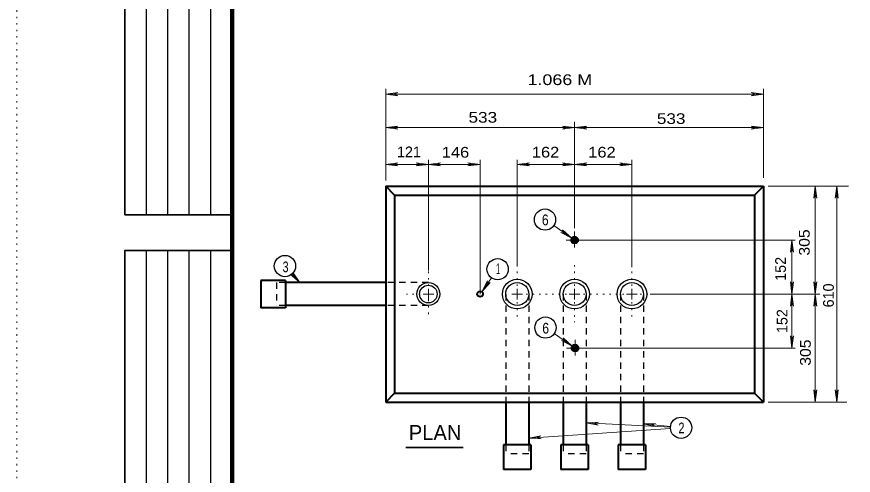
# Model space of a CAD drawing. Extents: x 312583 to 312854, y 144419 to 144597.
# Drawn here: x 312601.2 to 312660.6, y 144472.2 to 144504.7 of the extents above; entities that cross this region are included whole.
import ezdxf
from ezdxf.enums import TextEntityAlignment as Align

# ---------------------------------------------------------------- set-up
doc = ezdxf.new("R2010")
doc.units = 0
doc.header["$LTSCALE"] = 0.3
doc.linetypes.add('DOTTED', pattern=[1.5, 0.3, -1.2])
doc.linetypes.add('SHORT_DASHED', pattern=[2.7, 1.5, -1.2])
for name, color, linetype, lineweight in [('1', 7, 'Continuous', 25), ('2', 7, 'Continuous', 13), ('63', 7, 'DOTTED', 13)]:
    doc.layers.add(name, color=color, linetype=linetype, lineweight=lineweight)

msp = doc.modelspace()

# ---------------------------------------------------------------- linework, layer by layer
at = {"layer": '1'}
for p, q in [((312610.4087, 144490.6573), (312610.4087, 144521.8756)), ((312611.9315, 144490.6573), (312611.9315, 144521.8756)), ((312613.4543, 144490.6573), (312613.4543, 144521.8756)), ((312614.9772, 144490.6573), (312614.9772, 144521.8756)), ((312610.4087, 144456.901), (312610.4087, 144488.1192)), ((312611.9315, 144456.901), (312611.9315, 144488.1192)), ((312613.4543, 144456.901), (312613.4543, 144488.1192)), ((312614.9772, 144456.901), (312614.9772, 144488.1192))]:
    msp.add_line(p, q, dxfattribs=at)
at = {"layer": '1', "lineweight": 40}
for p, q in [((312627.4036, 144492.6869), (312654.237, 144492.6869)), ((312627.4036, 144492.6869), (312627.4036, 144477.3535)), ((312628.04, 144492.0505), (312627.4036, 144492.6869)), ((312653.6006, 144492.0505), (312654.237, 144492.6869)), ((312654.237, 144492.6869), (312654.237, 144477.3535)), ((312628.04, 144492.0505), (312653.6006, 144492.0505)), ((312628.04, 144492.0505), (312628.04, 144477.9975)), ((312653.6006, 144492.0505), (312653.6006, 144477.9975)), ((312620.2813, 144485.9939), (312618.5256, 144485.9939)), ((312618.5256, 144485.9939), (312618.5256, 144484.0465)), ((312620.2813, 144485.9939), (312620.2813, 144484.0465)), ((312627.4036, 144485.8329), (312620.2813, 144485.8329)), ((312620.2813, 144484.0465), (312618.5256, 144484.0465)), ((312627.4036, 144484.2075), (312620.2813, 144484.2075)), ((312627.4036, 144477.3535), (312628.04, 144477.9975)), ((312628.04, 144477.9975), (312653.6006, 144477.9975)), ((312653.6006, 144477.9975), (312654.237, 144477.3535)), ((312627.4036, 144477.3535), (312654.237, 144477.3535)), ((312635.929, 144477.3535), (312635.929, 144474.3175)), ((312637.562, 144477.3535), (312637.562, 144474.3175)), ((312640.0076, 144477.3535), (312640.0076, 144474.3175)), ((312641.633, 144477.3535), (312641.633, 144474.3175)), ((312644.0786, 144477.3535), (312644.0786, 144474.3175)), ((312645.704, 144477.3535), (312645.704, 144474.3175)), ((312635.7756, 144474.3175), (312635.7756, 144472.5619)), ((312637.723, 144474.3175), (312635.7756, 144474.3175)), ((312637.723, 144474.3175), (312637.723, 144472.5619)), ((312639.8466, 144474.3175), (312639.8466, 144472.5619)), ((312641.794, 144474.3175), (312639.8466, 144474.3175)), ((312641.794, 144474.3175), (312641.794, 144472.5619)), ((312643.9176, 144474.3175), (312643.9176, 144472.5619)), ((312645.865, 144474.3175), (312643.9176, 144474.3175)), ((312645.865, 144474.3175), (312645.865, 144472.5619)), ((312637.723, 144472.5619), (312635.7756, 144472.5619)), ((312641.794, 144472.5619), (312639.8466, 144472.5619)), ((312645.865, 144472.5619), (312643.9176, 144472.5619))]:
    msp.add_line(p, q, dxfattribs=at)
at = {"layer": '1', "linetype": 'SHORT_DASHED'}
for p, q in [((312619.645, 144485.8329), (312619.645, 144484.2075)), ((312620.2813, 144485.8329), (312619.645, 144485.8329)), ((312630.4396, 144485.8329), (312627.4036, 144485.8329)), ((312635.929, 144485.0202), (312635.929, 144477.3535)), ((312637.562, 144485.0202), (312637.562, 144477.3535)), ((312640.0076, 144485.0202), (312640.0076, 144477.3535)), ((312641.633, 144485.0202), (312641.633, 144477.3535)), ((312644.0786, 144485.0202), (312644.0786, 144477.3535)), ((312645.704, 144485.0202), (312645.704, 144477.3535)), ((312620.2813, 144484.2075), (312619.645, 144484.2075)), ((312630.4396, 144484.2075), (312627.4036, 144484.2075)), ((312635.929, 144474.3175), (312635.929, 144473.6812)), ((312637.562, 144474.3175), (312637.562, 144473.6812)), ((312640.0076, 144474.3175), (312640.0076, 144473.6812)), ((312641.633, 144474.3175), (312641.633, 144473.6812)), ((312644.0786, 144474.3175), (312644.0786, 144473.6812)), ((312645.704, 144474.3175), (312645.704, 144473.6812)), ((312637.562, 144473.6812), (312635.929, 144473.6812)), ((312641.633, 144473.6812), (312640.0076, 144473.6812)), ((312645.704, 144473.6812), (312644.0786, 144473.6812))]:
    msp.add_line(p, q, dxfattribs=at)
at = {"layer": '1', "lineweight": 158}
msp.add_lwpolyline([(312616.5, 144423.1446), (312616.5, 144585.0846), (312849, 144585.0846)], dxfattribs=at)
at = {"layer": '1', "lineweight": 35}
for points in [[(312616.5, 144490.6573), (312608.8858, 144490.6573), (312608.8858, 144521.8756), (312616.5, 144521.8756)], [(312616.5, 144456.901), (312608.8858, 144456.901), (312608.8858, 144488.1192), (312616.5, 144488.1192)]]:
    msp.add_lwpolyline(points, dxfattribs=at)
at = {"layer": '1', "lineweight": 40}
for centre, radius in [((312640.8197, 144488.8548), 0.2396), ((312640.8197, 144488.8548), 0.2156), ((312640.8197, 144488.8548), 0.1941), ((312640.8197, 144488.8548), 0.1747), ((312640.8197, 144488.8548), 0.1572), ((312640.8197, 144488.8548), 0.1415), ((312640.8197, 144488.8548), 0.1273), ((312640.8197, 144488.8548), 0.1146), ((312640.8197, 144488.8548), 0.1031), ((312640.8197, 144488.8548), 0.0928), ((312640.8197, 144488.8548), 0.0835), ((312640.8197, 144488.8548), 0.0752), ((312640.8197, 144488.8548), 0.0677), ((312640.8197, 144488.8548), 0.0609), ((312640.8197, 144488.8548), 0.0548), ((312634.1113, 144485.0215), 0.1996), ((312640.8516, 144481.1881), 0.2396), ((312640.8516, 144481.1881), 0.2156), ((312640.8516, 144481.1881), 0.1941), ((312640.8516, 144481.1881), 0.1747), ((312640.8516, 144481.1881), 0.1572), ((312640.8516, 144481.1881), 0.1415), ((312640.8516, 144481.1881), 0.1273), ((312640.8516, 144481.1881), 0.1146), ((312640.8516, 144481.1881), 0.1031), ((312640.8516, 144481.1881), 0.0928), ((312640.8516, 144481.1881), 0.0835), ((312640.8516, 144481.1881), 0.0752), ((312640.8516, 144481.1881), 0.0677), ((312640.8516, 144481.1881), 0.0609), ((312640.8516, 144481.1881), 0.0548)]:
    msp.add_circle(centre, radius, dxfattribs=at)
at = {"layer": '1'}
for centre, radius in [((312630.4377, 144485.0215), 0.8146), ((312636.7467, 144485.0215), 1.0542), ((312636.7467, 144485.0215), 0.8146), ((312640.8197, 144485.0215), 1.0542), ((312640.8197, 144485.0215), 0.8146), ((312644.8926, 144485.0215), 1.0542), ((312644.8926, 144485.0215), 0.8146), ((312630.4377, 144485.0215), 0.6232)]:
    msp.add_circle(centre, radius, dxfattribs=at)
at = {"layer": '2'}
for p, q in [((312627.4036, 144493.0855), (312627.4036, 144499.5792)), ((312627.4036, 144499.2112), (312628.27, 144499.3185)), ((312628.27, 144499.3185), (312627.994, 144499.2112)), ((312653.3706, 144499.3185), (312653.6466, 144499.2112)), ((312654.237, 144499.2112), (312653.3706, 144499.3185)), ((312654.237, 144493.2772), (312654.237, 144499.5792)), ((312627.4036, 144499.2112), (312654.237, 144499.2112)), ((312627.4036, 144499.2112), (312628.27, 144499.1039)), ((312628.27, 144499.1039), (312627.994, 144499.2112)), ((312653.3706, 144499.1039), (312653.6466, 144499.2112)), ((312654.237, 144499.2112), (312653.3706, 144499.1039)), ((312627.4036, 144496.8422), (312628.27, 144496.9495)), ((312628.27, 144496.9495), (312627.994, 144496.8422)), ((312639.954, 144496.9495), (312640.23, 144496.8422)), ((312640.8203, 144496.8422), (312639.954, 144496.9495)), ((312640.8203, 144489.6892), (312640.8203, 144497.2562)), ((312640.8203, 144496.8422), (312641.6866, 144496.9495)), ((312641.6866, 144496.9495), (312641.4106, 144496.8422)), ((312653.3706, 144496.9495), (312653.6466, 144496.8422)), ((312654.237, 144496.8422), (312653.3706, 144496.9495)), ((312627.4036, 144496.8422), (312628.27, 144496.7349)), ((312627.4036, 144496.8422), (312642.1006, 144496.8422)), ((312628.27, 144496.7349), (312627.994, 144496.8422)), ((312628.04, 144496.8422), (312640.8203, 144496.8422)), ((312639.954, 144496.7349), (312640.23, 144496.8422)), ((312640.8203, 144496.8422), (312639.954, 144496.7349)), ((312640.8203, 144496.8422), (312654.237, 144496.8422)), ((312640.8203, 144496.8422), (312641.6866, 144496.7349)), ((312641.6866, 144496.7349), (312641.4106, 144496.8422)), ((312653.3706, 144496.7349), (312653.6466, 144496.8422)), ((312654.237, 144496.8422), (312653.3706, 144496.7349)), ((312627.4036, 144494.2279), (312628.27, 144494.3352)), ((312627.4036, 144494.2279), (312630.4396, 144494.2279)), ((312627.4036, 144494.2279), (312628.27, 144494.1205)), ((312628.27, 144494.3352), (312627.994, 144494.2279)), ((312628.27, 144494.1205), (312627.994, 144494.2279)), ((312629.5733, 144494.3352), (312629.8493, 144494.2279)), ((312630.4396, 144494.2279), (312629.5733, 144494.3352)), ((312629.5733, 144494.1205), (312629.8493, 144494.2279)), ((312630.4396, 144494.2279), (312629.5733, 144494.1205)), ((312630.4396, 144486.6839), (312630.4396, 144494.5422)), ((312630.4396, 144494.2279), (312631.306, 144494.3352)), ((312630.4396, 144494.2279), (312634.112, 144494.2279)), ((312630.4396, 144494.2279), (312631.306, 144494.1205)), ((312631.306, 144494.3352), (312631.03, 144494.2279)), ((312631.306, 144494.1205), (312631.03, 144494.2279)), ((312633.2456, 144494.3352), (312633.5216, 144494.2279)), ((312634.112, 144494.2279), (312633.2456, 144494.3352)), ((312633.2456, 144494.1205), (312633.5216, 144494.2279)), ((312634.112, 144494.2279), (312633.2456, 144494.1205)), ((312634.112, 144485.0202), (312634.112, 144494.5422)), ((312636.7493, 144487.0059), (312636.7493, 144494.5422)), ((312636.7493, 144494.2279), (312637.6156, 144494.3352)), ((312636.7493, 144494.2279), (312637.6156, 144494.1205)), ((312636.7493, 144494.2279), (312640.8203, 144494.2279)), ((312637.6156, 144494.3352), (312637.3396, 144494.2279)), ((312637.6156, 144494.1205), (312637.3396, 144494.2279)), ((312639.954, 144494.3352), (312640.23, 144494.2279)), ((312640.8203, 144494.2279), (312639.954, 144494.3352)), ((312639.954, 144494.1205), (312640.23, 144494.2279)), ((312640.8203, 144494.2279), (312639.954, 144494.1205)), ((312640.8203, 144494.2279), (312641.6866, 144494.3352)), ((312640.8203, 144494.2279), (312644.8913, 144494.2279)), ((312640.8203, 144494.2279), (312641.6866, 144494.1205)), ((312641.6866, 144494.3352), (312641.4106, 144494.2279)), ((312641.6866, 144494.1205), (312641.4106, 144494.2279)), ((312644.025, 144494.3352), (312644.301, 144494.2279)), ((312644.8913, 144494.2279), (312644.025, 144494.3352)), ((312644.025, 144494.1205), (312644.301, 144494.2279)), ((312644.8913, 144494.2279), (312644.025, 144494.1205)), ((312644.8913, 144486.9215), (312644.8913, 144494.5422)), ((312654.5666, 144492.6869), (312660.2632, 144492.6869)), ((312657.9134, 144492.6869), (312657.8061, 144491.8205)), ((312657.9134, 144492.6869), (312658.0208, 144491.8205)), ((312659.4375, 144492.6869), (312659.3302, 144491.8205)), ((312659.4375, 144477.3535), (312659.4375, 144492.6869)), ((312659.4375, 144492.6869), (312659.5449, 144491.8205)), ((312657.8061, 144491.8205), (312657.9134, 144492.0965)), ((312658.0208, 144491.8205), (312657.9134, 144492.0965)), ((312659.3302, 144491.8205), (312659.4375, 144492.0965)), ((312659.5449, 144491.8205), (312659.4375, 144492.0965)), ((312639.3406, 144489.8809), (312640.621, 144488.9915)), ((312639.8466, 144489.3979), (312640.138, 144489.3289)), ((312640.621, 144488.9915), (312639.8466, 144489.3979)), ((312639.9693, 144489.5742), (312640.138, 144489.3289)), ((312640.621, 144488.9915), (312639.9693, 144489.5742)), ((312640.8203, 144488.3245), (312640.8203, 144489.4515)), ((312641.3493, 144488.8535), (312640.2223, 144488.8535)), ((312640.943, 144488.8535), (312656.491, 144488.8535)), ((312656.261, 144488.8535), (312656.1536, 144487.9872)), ((312656.261, 144488.8535), (312656.3683, 144487.9872)), ((312656.1536, 144487.9872), (312656.261, 144488.2632)), ((312656.3683, 144487.9872), (312656.261, 144488.2632)), ((312620.6493, 144486.4079), (312620.9176, 144486.2775)), ((312621.3163, 144485.8329), (312620.6493, 144486.4079)), ((312620.7566, 144486.4539), (312621.3163, 144485.8329)), ((312620.8103, 144486.5535), (312620.9176, 144486.2775)), ((312621.3163, 144485.8329), (312620.8103, 144486.5535)), ((312634.917, 144486.1702), (312634.227, 144485.1812)), ((312634.227, 144485.1812), (312634.641, 144485.9555)), ((312634.227, 144485.1812), (312634.8173, 144485.8329)), ((312634.641, 144485.9555), (312634.5643, 144485.6642)), ((312634.8173, 144485.8329), (312634.5643, 144485.6642)), ((312656.1536, 144485.8865), (312656.261, 144485.6105)), ((312656.261, 144485.0202), (312656.1536, 144485.8865)), ((312656.3683, 144485.8865), (312656.261, 144485.6105)), ((312656.261, 144485.0202), (312656.3683, 144485.8865)), ((312657.8061, 144485.8865), (312657.9134, 144485.6105)), ((312657.9134, 144485.0202), (312657.8061, 144485.8865)), ((312658.0208, 144485.8865), (312657.9134, 144485.6105)), ((312657.9134, 144485.0202), (312658.0208, 144485.8865)), ((312630.4396, 144485.0202), (312630.4396, 144485.4035)), ((312636.7493, 144485.0202), (312636.7493, 144485.4035)), ((312640.8203, 144485.0202), (312640.8203, 144485.4035)), ((312644.8913, 144485.0202), (312644.8913, 144485.4035)), ((312630.4396, 144485.0202), (312630.0563, 144485.0202)), ((312630.4396, 144485.0202), (312630.823, 144485.0202)), ((312630.4396, 144485.0202), (312630.4396, 144484.6369)), ((312636.7493, 144485.0202), (312636.366, 144485.0202)), ((312636.7493, 144485.0202), (312637.1326, 144485.0202)), ((312636.7493, 144485.0202), (312636.7493, 144484.6369)), ((312640.8203, 144485.0202), (312640.437, 144485.0202)), ((312640.8203, 144485.0202), (312641.2036, 144485.0202)), ((312640.8203, 144485.0202), (312640.8203, 144484.6369)), ((312644.8913, 144485.0202), (312644.508, 144485.0202)), ((312644.8913, 144485.0202), (312645.2746, 144485.0202)), ((312644.8913, 144485.0202), (312644.8913, 144484.6369)), ((312646.1946, 144485.0202), (312658.2457, 144485.0202)), ((312656.261, 144485.0202), (312656.1536, 144484.1539)), ((312656.261, 144485.0202), (312656.3683, 144484.1539)), ((312657.9134, 144485.0202), (312657.8061, 144484.1539)), ((312657.9134, 144485.0202), (312658.0208, 144484.1539)), ((312659.4375, 144477.3535), (312659.4375, 144485.0202)), ((312656.1536, 144484.1539), (312656.261, 144484.4299)), ((312656.3683, 144484.1539), (312656.261, 144484.4299)), ((312657.8061, 144484.1539), (312657.9134, 144484.4299)), ((312658.0208, 144484.1539), (312657.9134, 144484.4299)), ((312639.3713, 144482.2142), (312640.6516, 144481.3249)), ((312639.885, 144481.7312), (312640.1686, 144481.6622)), ((312640.6516, 144481.3249), (312639.885, 144481.7312)), ((312640.0076, 144481.9075), (312640.1686, 144481.6622)), ((312640.6516, 144481.3249), (312640.0076, 144481.9075)), ((312640.851, 144480.6579), (312640.851, 144481.7849)), ((312656.1536, 144482.0532), (312656.261, 144481.7772)), ((312656.261, 144481.1869), (312656.1536, 144482.0532)), ((312656.3683, 144482.0532), (312656.261, 144481.7772)), ((312656.261, 144481.1869), (312656.3683, 144482.0532)), ((312641.38, 144481.1869), (312640.253, 144481.1869)), ((312640.943, 144481.1869), (312656.491, 144481.1869)), ((312657.8061, 144478.2199), (312657.9134, 144477.9439)), ((312657.9134, 144477.3535), (312657.8061, 144478.2199)), ((312658.0208, 144478.2199), (312657.9134, 144477.9439)), ((312657.9134, 144477.3535), (312658.0208, 144478.2199)), ((312659.3302, 144478.2199), (312659.4375, 144477.9439)), ((312659.4375, 144477.3535), (312659.3302, 144478.2199)), ((312659.3302, 144478.2199), (312659.4375, 144477.9439)), ((312659.4375, 144477.3535), (312659.3302, 144478.2199)), ((312659.5449, 144478.2199), (312659.4375, 144477.9439)), ((312659.4375, 144477.3535), (312659.5449, 144478.2199)), ((312659.5449, 144478.2199), (312659.4375, 144477.9439)), ((312659.4375, 144477.3535), (312659.5449, 144478.2199)), ((312654.5666, 144477.3535), (312660.1511, 144477.3535)), ((312641.633, 144475.8739), (312642.507, 144475.9352)), ((312641.633, 144475.8739), (312647.6283, 144475.5672)), ((312641.633, 144475.8739), (312642.4916, 144475.7205)), ((312642.507, 144475.9352), (312642.2233, 144475.8432)), ((312642.4916, 144475.7205), (312642.2233, 144475.8432)), ((312645.704, 144475.8202), (312646.578, 144475.8355)), ((312647.636, 144475.6132), (312645.704, 144475.8202)), ((312645.704, 144475.8202), (312646.555, 144475.6209)), ((312646.578, 144475.8355), (312646.2943, 144475.7589)), ((312646.555, 144475.6209), (312646.2943, 144475.7589)), ((312647.6283, 144475.4752), (312637.562, 144474.8005)), ((312637.562, 144474.8005), (312638.4206, 144474.9692)), ((312638.4206, 144474.9692), (312638.1523, 144474.8465)), ((312637.562, 144474.8005), (312638.436, 144474.7545)), ((312638.436, 144474.7545), (312638.1523, 144474.8465))]:
    msp.add_line(p, q, dxfattribs=at)
at = {"layer": '2', "linetype": 'DOTTED'}
for p, q in [((312636.7493, 144485.5952), (312636.7493, 144487.0059)), ((312640.8203, 144485.5952), (312640.8203, 144487.0672)), ((312644.8913, 144485.5952), (312644.8913, 144486.9215)), ((312630.4396, 144485.5952), (312630.4396, 144486.6839)), ((312629.8646, 144485.0202), (312628.8756, 144485.0202)), ((312630.4396, 144483.6019), (312630.4396, 144484.6369)), ((312640.2453, 144485.0202), (312637.3703, 144485.0202)), ((312644.3163, 144485.0202), (312641.4183, 144485.0202)), ((312645.4663, 144485.0202), (312646.8386, 144485.0202)), ((312636.7493, 144484.4452), (312636.7493, 144483.1572)), ((312640.8203, 144484.4452), (312640.8203, 144483.0345)), ((312644.8913, 144484.4452), (312644.8913, 144483.1265))]:
    msp.add_line(p, q, dxfattribs=at)
at = {"layer": '2', "lineweight": 35}
msp.add_line((312628.8307, 144474.1352), (312632.9029, 144474.1352), dxfattribs=at)
at = {"layer": '2'}
for points in [[(312657.9134, 144477.3535), (312657.9134, 144485.0202), (312657.9134, 144492.6869)], [(312656.261, 144481.1869), (312656.261, 144485.0202), (312656.261, 144488.8535)]]:
    msp.add_lwpolyline(points, dxfattribs=at)
at = {"layer": '2', "lineweight": 25}
for centre in [(312638.7209, 144490.3115), (312620.25, 144487.011), (312635.354, 144486.788), (312638.7529, 144482.6448), (312648.3854, 144475.5289)]:
    msp.add_circle(centre, 0.7557, dxfattribs=at)
at = {"layer": '63'}
msp.add_line((312601.2, 144418.5846), (312601.2, 144596.7846), dxfattribs=at)

# ---------------------------------------------------------------- texts
at = {"layer": '2'}
for s, width, p in [('1.066 M', 1.25, (312637.4781, 144499.8573)), ('533 ', 1.2, (312633.2856, 144497.1865)), ('533 ', 1.2, (312646.6619, 144497.0945)), ('146 ', 1.15, (312631.386, 144494.7045)), ('162 ', 1.15, (312637.7842, 144494.7131)), ('162 ', 1.15, (312641.7889, 144494.7131)), ('6', 0.85, (312638.4979, 144489.9054)), ('3', 0.75, (312620.0827, 144486.5713)), ('1', 0.5, (312635.2441, 144486.4425)), ('6', 0.85, (312638.5286, 144482.22)), ('2', 0.75, (312648.2006, 144475.1428))]:
    msp.add_text(s, height=0.76, dxfattribs=dict(at, width=width)).set_placement(p)
msp.add_text('121 ', height=0.76, dxfattribs=at).set_placement((312628.2078, 144494.735))
at = {"layer": '2', "width": 1.1}
for p in [(312657.518, 144487.751), (312657.5926, 144479.932)]:
    msp.add_text('305', height=0.76, rotation=90, dxfattribs=at).set_placement(p)
at = {"layer": '2'}
for s, p in [('152', (312655.8282, 144485.9626)), ('610', (312659.2318, 144484.0771)), ('152', (312655.9403, 144482.2555))]:
    msp.add_text(s, height=0.76, rotation=90, dxfattribs=at).set_placement(p)
msp.add_text('PLAN', height=1.07, dxfattribs=at).set_placement((312630.9155, 144474.6549), align=Align.CENTER)

doc.saveas('drawing.dxf')
